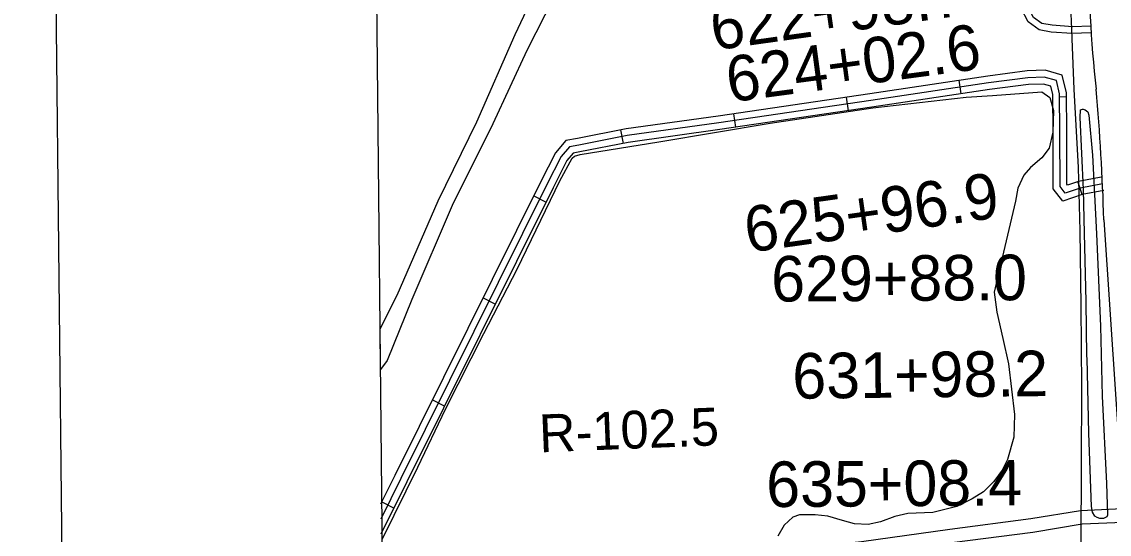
# Model space of a CAD drawing. Extents: x 3651524 to 3689615, y 505651 to 531377.
# Drawn here: x 3654864 to 3657251, y 521661 to 522786 of the extents above; entities that cross this region are included whole.
import ezdxf

# ---------------------------------------------------------------- set-up
doc = ezdxf.new("R2010")
doc.units = 0
for name, color, linetype in [('V-ANNO-SYMB', 7, 'Continuous'), ('V-GRID-FRAM', 7, 'Continuous'), ('V-RAIL-TRAK', 7, 'Continuous'), ('V-RIVR-RANG-IDEN', 7, 'Continuous'), ('V-ROAD-CNTR', 7, 'Continuous'), ('V-SITE-VEGE', 7, 'Continuous'), ('V-SURV-IDEN', 7, 'Continuous')]:
    doc.layers.add(name, color=color, linetype=linetype)

msp = doc.modelspace()

# ---------------------------------------------------------------- linework, layer by layer
at = {"layer": 'V-ANNO-SYMB'}
msp.add_lwpolyline([(3655110.709, 506888.512), (3688191.993, 507244.585), (3687945.344, 530159.832), (3654864.059, 529803.76), (3655110.709, 506888.512)], dxfattribs=at)
at = {"layer": 'V-GRID-FRAM'}
msp.add_lwpolyline([(3655577.191, 529244.355), (3687244.414, 529585.207), (3687448.048, 511403.469), (3655764.959, 511062.446), (3655577.191, 529244.355)], dxfattribs=at)
at = {"layer": 'V-RAIL-TRAK'}
msp.add_lwpolyline([(3657166.337, 522820.885), (3657168.336, 522769.878), (3657169.186, 522748.21), (3657173.739, 522638.306), (3657183.098, 522466.319), (3657186.541, 522326.914), (3657188.941, 522162.134), (3657189.924, 521983.802), (3657189.291, 521814.355), (3657188.503, 521636.054)], dxfattribs=at)
at = {"layer": 'V-ROAD-CNTR'}
for p, q in [((3656925.988, 522627.815), (3656921.513, 522657.479)), ((3656678.702, 522590.709), (3656674.338, 522620.39)), ((3657140.842, 522621.583), (3657157.21, 522621.737)), ((3656431.36, 522554.348), (3656426.997, 522584.029)), ((3656184.634, 522519.114), (3656178.789, 522548.539)), ((3657191.983, 522406.67), (3657182.531, 522435.142)), ((3656014.523, 522390.279), (3655987.655, 522403.625)), ((3655903.314, 522166.377), (3655876.446, 522179.722)), ((3655792.106, 521942.474), (3655765.238, 521955.819)), ((3655680.977, 521718.553), (3655654.092, 521731.866))]:
    msp.add_line(p, q, dxfattribs=at)
for points in [[(3657210.612, 522776.446), (3657170.269, 522775.129), (3657125.793, 522778.319), (3657103.339, 522782.249), (3657084.7, 522795.677), (3657072.003, 522820.879), (3657054.847, 522880.378), (3657039.152, 522929.179), (3657005.884, 523017.073), (3656978.501, 523093.865), (3656949.267, 523160.123), (3656919.192, 523218.637), (3656894.561, 523295.521), (3656846.057, 523467.78), (3656800.962, 523555.001)], [(3657211.101, 522761.454), (3657169.976, 522760.111), (3657123.959, 522763.412), (3657097.363, 522768.067), (3657072.955, 522785.651), (3657057.978, 522815.379), (3657040.497, 522876.003), (3657031.647, 522903.52)], [(3657233.603, 522444.954), (3657183.915, 522435.601), (3657159.786, 522427.591), (3657158.191, 522429.65), (3657158.054, 522543.647), (3657157.12, 522630.018), (3657147.619, 522668.823), (3657110.556, 522679.554), (3657071.12, 522678.228), (3656984.375, 522666.962), (3656725.692, 522627.939), (3656392.373, 522578.939), (3656190.421, 522550.85), (3656083.912, 522529.692), (3656058.506, 522525.385), (3656035.492, 522498.621), (3656003.371, 522435.268), (3655682.768, 521789.775), (3655651.839, 521727.315)], [(3657236.378, 522430.213), (3657187.682, 522421.047), (3657154.432, 522410.009), (3657143.197, 522424.512), (3657143.054, 522543.557), (3657142.14, 522628.129), (3657135.113, 522656.828), (3657108.676, 522664.482), (3657072.341, 522663.261), (3656986.46, 522652.107), (3656727.902, 522613.103), (3656394.497, 522564.09), (3656192.918, 522536.053), (3656086.627, 522514.938), (3656066.35, 522511.501), (3656048.05, 522490.218), (3656016.778, 522428.54), (3655696.206, 521783.111), (3655652.181, 521694.203)], [(3657239.153, 522415.472), (3657191.449, 522406.493), (3657149.078, 522392.427), (3657128.203, 522419.374), (3657128.054, 522543.467), (3657127.16, 522626.24), (3657122.607, 522644.833), (3657106.796, 522649.41), (3657073.562, 522648.294), (3656988.545, 522637.252), (3656730.112, 522598.267), (3656396.621, 522549.241), (3656195.415, 522521.256), (3656089.342, 522500.184), (3656074.194, 522497.617), (3656060.608, 522481.815), (3656030.185, 522421.812), (3655709.644, 521776.447), (3655652.523, 521661.092)], [(3657239.359, 522351.134), (3657278.501, 521760.51)], [(3656091.376, 520420.712), (3656178.838, 520609.739), (3656387.375, 521073.241), (3656497.513, 521355.617), (3656562.089, 521495.516), (3656605.216, 521596.409), (3656632.471, 521637.271), (3656707.597, 521644.943), (3656901.305, 521672.375), (3657079.205, 521695.424), (3657188.361, 521713.506), (3657280.524, 521717.529)], [(3656430.857, 521102.163), (3656525.133, 521343.869), (3656589.507, 521483.332), (3656631.712, 521582.069), (3656649.583, 521608.863), (3656711.225, 521615.157), (3656905.335, 521642.647), (3657083.585, 521665.74), (3657191.477, 521683.614), (3657281.832, 521687.557)]]:
    msp.add_lwpolyline(points, dxfattribs=at)
for centre, radius, start, end in [((3659987.166, 522940.666), 2781.407, 179.684128, 186.247442), ((3652464.901, 522210.752), 4776.522, 1.684172, 5.131666)]:
    msp.add_arc(centre, radius, start, end, dxfattribs=at)
at = {"layer": 'V-SITE-VEGE'}
for p, q in [((3655947.337, 522758.413), (3656021.489, 522918.006)), ((3656053.139, 522880.579), (3655972.413, 522722.641)), ((3655863.117, 522566.52), (3655947.337, 522758.413)), ((3655972.413, 522722.641), (3655898.283, 522561.859)), ((3656732.194, 522597.232), (3656937.426, 522620.337)), ((3656937.426, 522620.337), (3656994.59, 522623.845)), ((3656994.59, 522623.845), (3657102.927, 522632.531)), ((3657102.927, 522632.531), (3657120.468, 522619.758)), ((3657120.468, 522619.758), (3657128.777, 522591.307)), ((3656506.898, 522563.597), (3656732.194, 522597.232)), ((3657128.777, 522591.307), (3657127.329, 522543.58)), ((3655777.941, 522393.038), (3655863.117, 522566.52)), ((3656262.672, 522522.435), (3656506.898, 522563.597)), ((3655898.283, 522561.859), (3655809.062, 522382.353)), ((3657127.329, 522543.58), (3657119.08, 522508.244)), ((3656089.726, 522494.598), (3656262.672, 522522.435)), ((3656077.268, 522491.37), (3656089.726, 522494.598)), ((3657119.08, 522508.244), (3657103.386, 522487.664)), ((3656044.949, 522437.08), (3656071.999, 522486.498)), ((3656071.999, 522486.498), (3656077.268, 522491.37)), ((3657103.386, 522487.664), (3657078.169, 522466.303)), ((3657063.597, 522449.323), (3657050.451, 522420.448)), ((3657078.169, 522466.303), (3657063.597, 522449.323)), ((3655951.572, 522243.274), (3656044.949, 522437.08)), ((3657050.451, 522420.448), (3657045.639, 522392.331)), ((3655688.071, 522186.171), (3655777.941, 522393.038)), ((3655809.062, 522382.353), (3655720.359, 522176.697)), ((3657045.639, 522392.331), (3657013.155, 522255.168)), ((3657013.155, 522255.168), (3656998.293, 522192.274)), ((3655878.637, 522101.736), (3655951.572, 522243.274)), ((3655650.848, 522111.993), (3655688.071, 522186.171)), ((3656998.293, 522192.274), (3657004.523, 522148.279)), ((3655720.359, 522176.697), (3655666.03, 522042.324)), ((3657004.523, 522148.279), (3657017.577, 522090.706)), ((3655651.767, 522023.015), (3655650.848, 522111.993)), ((3655794.257, 521935.531), (3655878.637, 522101.736)), ((3657017.577, 522090.706), (3657029.988, 522035.502)), ((3655666.03, 522042.324), (3655651.767, 522023.015)), ((3657029.988, 522035.502), (3657042.902, 521924.269)), ((3655733.565, 521807.947), (3655794.257, 521935.531)), ((3657042.902, 521924.269), (3657042.095, 521874.173)), ((3657042.095, 521874.173), (3657028.157, 521825.013)), ((3657028.157, 521825.013), (3657016.096, 521801.524)), ((3655655.609, 521650.971), (3655733.565, 521807.947)), ((3657016.096, 521801.524), (3656997.506, 521776.715)), ((3656997.506, 521776.715), (3656975.292, 521754.219)), ((3656975.292, 521754.219), (3656950.554, 521738.829)), ((3656950.554, 521738.829), (3656916.305, 521722.06)), ((3656808.693, 521706.833), (3656780.799, 521700.322)), ((3656864.094, 521709.11), (3656808.693, 521706.833)), ((3656916.305, 521722.06), (3656864.094, 521709.11)), ((3656537.331, 521681.235), (3656523.509, 521656.518)), ((3656556.66, 521698.903), (3656537.331, 521681.235)), ((3656571.477, 521703.366), (3656556.66, 521698.903)), ((3656605.448, 521704.035), (3656571.477, 521703.366)), ((3656633.528, 521701.008), (3656605.448, 521704.035)), ((3656665.921, 521690.914), (3656633.528, 521701.008)), ((3656692.283, 521684.276), (3656665.921, 521690.914)), ((3656722.126, 521682.476), (3656692.283, 521684.276)), ((3656748.84, 521688.366), (3656722.126, 521682.476)), ((3656780.799, 521700.322), (3656748.84, 521688.366))]:
    msp.add_line(p, q, dxfattribs=at)
msp.add_lwpolyline([(3657202.018, 522051.335), (3657200.369, 522171.624), (3657196.558, 522322.152), (3657195.018, 522418.173), (3657187.018, 522575.787), (3657187.852, 522592.488), (3657192.193, 522594.031), (3657193.813, 522594.002), (3657198.104, 522592.847), (3657203.959, 522588.429), (3657206.521, 522580.833), (3657214.682, 522493.326), (3657222.954, 522320.608), (3657231.775, 522117.68), (3657235.535, 521964.457), (3657245.083, 521772.301), (3657247.639, 521703.228), (3657245.953, 521699.483), (3657241.593, 521696.863), (3657238.88, 521695.833), (3657230.792, 521695.976), (3657224.89, 521697.699), (3657219.549, 521700.488), (3657214.308, 521709.211), (3657212.37, 521721.646), (3657206.593, 521882.996), (3657202.491, 522047.55)], close=True, dxfattribs=at)

# ---------------------------------------------------------------- texts
at = {"layer": 'V-RIVR-RANG-IDEN'}
msp.add_text('R-102.5', height=83, rotation=2.323506, dxfattribs=at).set_placement((3656001.243, 521840.656))
at = {"layer": 'V-SURV-IDEN'}
for s, rotation, p in [('622+98.7', 8.05204, (3656382.953, 522722.875)), ('624+02.6', 7.617778, (3656417.273, 522608.813)), ('625+96.9', 8.025064, (3656457.785, 522278.874)), ('629+88.0', 0.334737, (3656509.337, 522171.698)), ('631+98.2', 0.6055, (3656555.959, 521958.47)), ('635+08.4', 0.390707, (3656498.499, 521720.594))]:
    msp.add_text(s, height=100, rotation=rotation, dxfattribs=at).set_placement(p)

doc.saveas('drawing.dxf')
